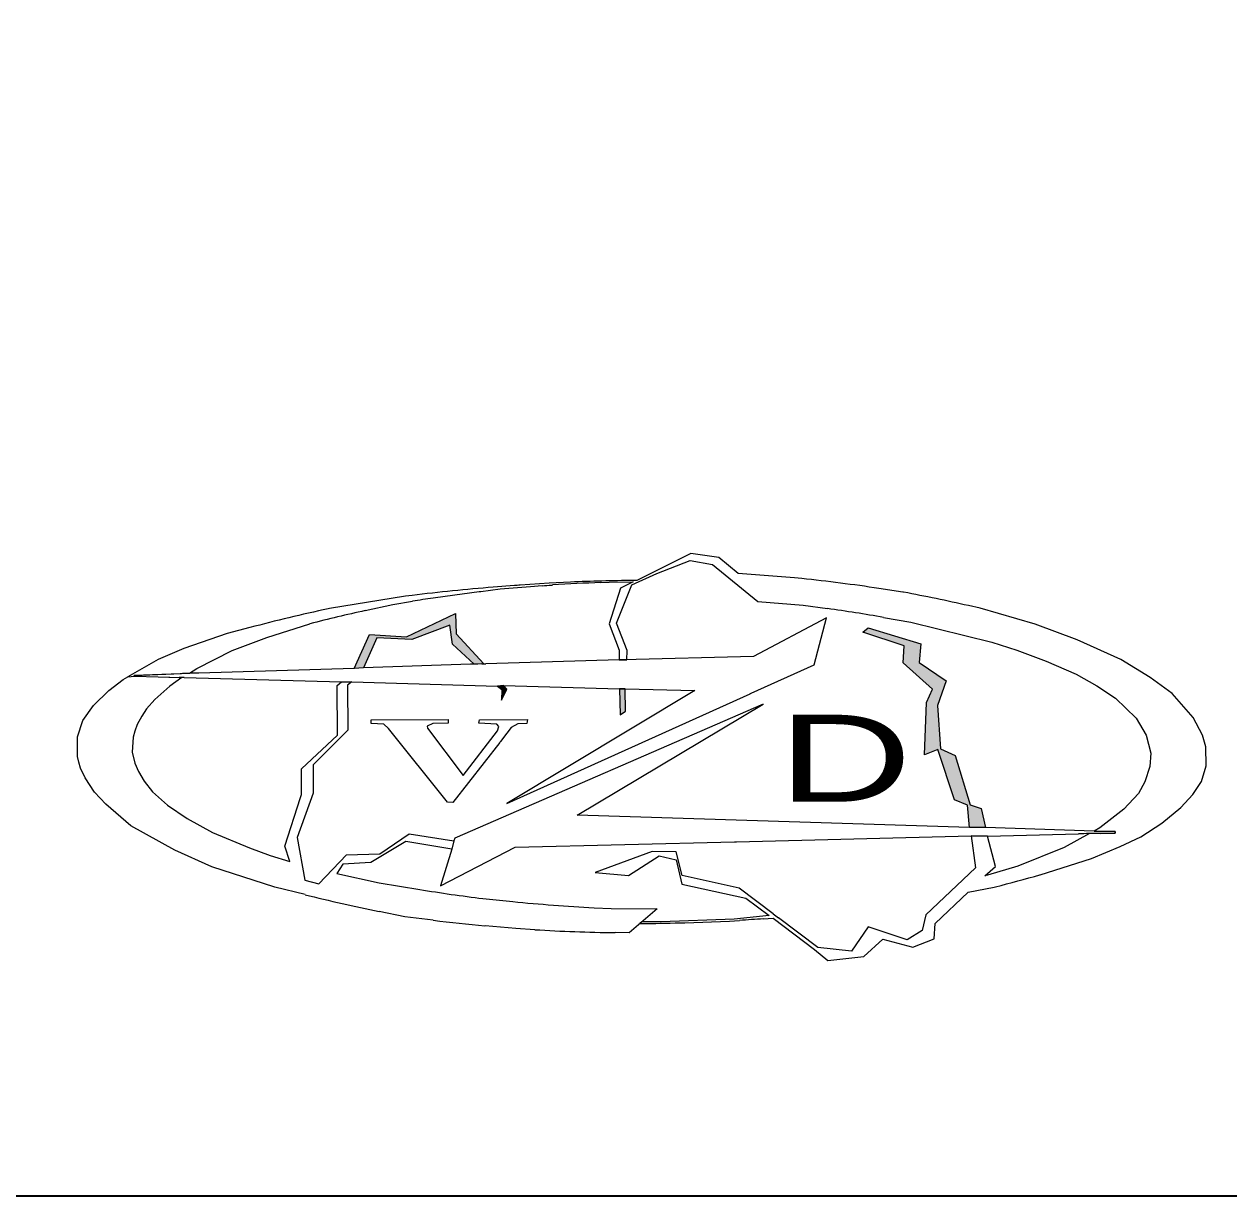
# Model space of a CAD drawing. Extents: x 308460 to 314812, y 245206 to 253414.
# Drawn here: x 314169.2 to 314384.6, y 245420.8 to 245630.3 of the extents above; entities that cross this region are included whole.
import ezdxf
from ezdxf.enums import TextEntityAlignment as Align

# ---------------------------------------------------------------- set-up
doc = ezdxf.new("R2010")
doc.units = 0
doc.header["$LTSCALE"] = 11
doc.layers.add('57', color=7, linetype='Continuous', lineweight=13)

msp = doc.modelspace()

# ---------------------------------------------------------------- hatches: boundary and pattern name
at = {"layer": '57'}
for points in [[(314229.92, 245515.24), (314228.22, 245515.09), (314230.98, 245521.15), (314237.58, 245520.76), (314246.36, 245524.93), (314246.46, 245521.3), (314251.41, 245515.91), (314249.66, 245515.86), (314245.78, 245519.45), (314245.34, 245522.85), (314238.55, 245520.28), (314232.29, 245520.57)], [(314341.08, 245486.67), (314338.25, 245486.67), (314337.84, 245490.68), (314335.54, 245491.62), (314332.59, 245500.58), (314330.17, 245499.64), (314330.52, 245509.01), (314331.59, 245511.42), (314326.34, 245516.08), (314326.57, 245519.14), (314319.14, 245521.56), (314320.09, 245522.38), (314329.52, 245519.49), (314329.23, 245516.14), (314334.06, 245512.9), (314332.53, 245508.48), (314333.06, 245500.7), (314335.65, 245499.52), (314338.37, 245490.74), (314340.31, 245490.03)], [(314254.93, 245512.08), (314253.88, 245511.95), (314254.62, 245511.35), (314254.57, 245509.44), (314255.5, 245511.4)], [(314276.66, 245511.43), (314275.65, 245511.44), (314275.77, 245506.8), (314276.71, 245507.47)]]:
    msp.add_hatch(color=256, dxfattribs=at).paths.add_polyline_path(points)

# ---------------------------------------------------------------- linework, layer by layer
for p, q in [((314256.87, 245529.91), (314253.1, 245529.62)), ((314263.49, 245530.01), (314263.7, 245530.02)), ((314251.07, 245515.9), (314250.31, 245515.88)), ((314271.12, 245472.32), (314274.18, 245472.16))]:
    msp.add_line(p, q, dxfattribs=at)
at = {"layer": '57', "lineweight": 35}
msp.add_lwpolyline([(314811.5, 253140.4), (312000.01, 253140.4), (312000.01, 245420.78), (314811.5, 245420.78)], close=True, dxfattribs=at)
at = {"layer": '57'}
for points in [[(314308.25, 245531.17), (314306.96, 245531.3), (314296.88, 245532.09), (314293.43, 245534.96), (314288.39, 245535.64), (314278.78, 245530.83), (314278.1, 245530.83)], [(314272.34, 245530.47), (314273.83, 245530.52), (314278.13, 245530.61), (314275.85, 245529.43), (314273.79, 245523.08), (314275.59, 245518.35), (314275.63, 245516.64), (314276.99, 245516.64), (314277.03, 245518.3), (314275.1, 245523.17), (314277.86, 245530.04), (314282.34, 245532.1), (314288.32, 245534.38), (314292.31, 245533.68), (314300.4, 245527.06), (314308.48, 245526.41), (314312.84, 245525.8)], [(314250.9, 245528.88), (314254.32, 245529.34), (314259.76, 245529.78), (314261.85, 245529.91)], [(314266.89, 245530.53), (314263.09, 245530.36), (314257.91, 245529.99)], [(314326.45, 245528.74), (314326.3, 245528.76), (314322.03, 245529.41)], [(314238.58, 245528.16), (314237.41, 245528.02), (314223.81, 245525.82), (314223.58, 245525.77)], [(314230.21, 245525.45), (314235.16, 245526.54), (314238.65, 245527.11)], [(314242.34, 245527.7), (314244.52, 245528.03), (314250.59, 245528.84)], [(314350.82, 245478.19), (314350.83, 245478.19), (314360.03, 245481.09), (314365.17, 245483.27), (314368.87, 245485.01), (314372.62, 245487.41), (314376.01, 245490.26), (314378.14, 245492.56), (314379.7, 245494.91), (314380.54, 245497.68), (314380.49, 245501.1), (314379.87, 245503.17), (314378.19, 245506.35), (314374.44, 245510.61), (314370.53, 245513.51), (314365.28, 245516.7), (314357.5, 245520.22), (314349.96, 245523), (314340.13, 245525.86), (314338.02, 245526.34)], [(314209.6, 245522.42), (314205.5, 245521.33), (314197.79, 245518.68), (314193.2, 245516.7), (314187.76, 245513.6), (314188.93, 245513.7), (314188.93, 245513.84), (314198.8, 245514.23), (314200.1, 245515.11), (314206.41, 245518.3), (314212.61, 245520.62), (314220.28, 245523.08), (314220.33, 245523.09)], [(314299.2, 245510.67), (314310.44, 245515.76), (314312.68, 245524.15), (314299.61, 245517.25), (314276.31, 245516.64), (314275.63, 245516.64), (314251.75, 245515.92)], [(314322.86, 245524.23), (314327.71, 245523.39), (314342.2, 245519.79), (314346.67, 245518.39), (314351.93, 245516.38), (314357.28, 245514.1), (314360.96, 245512), (314364.34, 245509.81), (314368, 245506.19), (314369.8, 245503.2), (314370.62, 245499.98), (314370.47, 245497.58), (314369.57, 245494.81), (314368.45, 245492.71), (314365.83, 245489.95), (314361.55, 245486.58), (314360.49, 245485.99), (314364.25, 245485.96), (314364.25, 245485.64), (314359.66, 245485.58), (314355.17, 245483.06), (314346.87, 245479.73), (314341.47, 245478.13), (314340.96, 245478.01), (314342.85, 245479.68), (314341.42, 245485.13), (314338.55, 245485.18), (314339.29, 245479.45), (314330.42, 245471.07), (314329.74, 245468.26), (314327.1, 245466.6), (314320.09, 245468.89), (314317.15, 245464.55), (314311.12, 245465.23), (314304.1, 245470.48)], [(314197.14, 245514.16), (314193.87, 245514.03), (314188.93, 245513.84), (314188.99, 245513.7), (314193.19, 245513.6), (314196.97, 245513.5)], [(314249.02, 245515.85), (314229.92, 245515.24), (314228.22, 245515.09), (314200.47, 245514.28)], [(314219.45, 245474.65), (314214.05, 245475.99), (314202.81, 245479.61), (314196.19, 245482.61), (314188.33, 245486.98), (314183.83, 245490.85), (314181.8, 245493), (314180.15, 245495.55), (314179.29, 245497.26), (314179.03, 245498.37), (314178.76, 245499.38), (314178.76, 245502.9), (314179.72, 245505.77), (314181.64, 245508.49), (314184.35, 245511.15), (314186.96, 245513.12), (314187.76, 245513.6), (314188.99, 245513.7), (314197.4, 245513.49), (314195.27, 245511.95), (314192.61, 245509.55), (314191.12, 245507.9), (314190.27, 245506.57), (314189.47, 245505.08), (314189.04, 245503.86), (314188.72, 245502.84), (314188.56, 245500.13), (314189.03, 245498.16), (314189.67, 245496.67), (314190.68, 245494.97), (314192.17, 245493.05), (314194.84, 245490.65), (314198.35, 245488.26), (314202.91, 245485.76), (314209.52, 245483), (314213.19, 245481.67), (314216.76, 245480.55), (314215.82, 245483.33), (314218.64, 245492.04), (314218.79, 245492.59), (314218.84, 245497.13), (314225.27, 245503.19), (314225.21, 245512.04), (314225.94, 245512.69), (314227.81, 245512.69), (314227.06, 245512.13), (314227.12, 245504.04), (314220.88, 245497.88), (314220.88, 245492.78), (314218.02, 245484.9), (314219.39, 245477.25), (314221.94, 245476.56), (314226.86, 245481.79), (314232.84, 245481.97), (314238.07, 245485.52), (314246.05, 245484.3), (314245.66, 245482.78), (314237.48, 245484.18), (314231.23, 245480.43), (314226.23, 245480.13), (314225.15, 245478.41), (314232.72, 245476.74), (314239.95, 245475.57)], [(314197.84, 245513.48), (314225.94, 245512.69), (314227.81, 245512.69), (314253.88, 245511.95), (314254.93, 245512.08), (314275.65, 245511.44), (314276.66, 245511.43), (314289.11, 245511.18), (314255.5, 245490.94), (314298.99, 245510.58)], [(314301.35, 245508.74), (314246.22, 245484.77), (314246.05, 245484.3), (314245.66, 245482.78), (314243.65, 245476.21), (314256.99, 245483.15), (314296.2, 245484.11)], [(314361.63, 245485.61), (314364.25, 245485.64), (314364.25, 245485.96), (314360.49, 245485.99), (314341.08, 245486.67), (314338.25, 245486.67), (314268.11, 245488.88), (314301.35, 245508.74)], [(314231.24, 245505.27), (314231.24, 245505.9), (314245.03, 245505.96), (314245.03, 245505.33), (314242.29, 245505.28), (314241.26, 245504.76), (314241.32, 245504.42), (314247.71, 245495.93), (314253.86, 245503.96), (314254.09, 245504.71), (314253.75, 245505.11), (314250.5, 245505.33), (314250.61, 245505.9), (314259.23, 245505.96), (314259.11, 245505.28), (314257.46, 245505.22), (314256.32, 245504.54), (314255.52, 245503.51), (314254.39, 245502.06)], [(314254.25, 245501.88), (314245.88, 245491.14), (314244.91, 245491.2), (314234.36, 245504.36), (314233.56, 245505.11), (314231.24, 245505.27)], [(314296.57, 245484.11), (314338.55, 245485.18), (314341.42, 245485.13), (314357.7, 245485.54)], [(314281.48, 245482.38), (314271.34, 245478.6), (314277.26, 245478.1), (314282.78, 245481.62), (314285.79, 245480.9), (314286.82, 245476.55), (314298.23, 245474.02), (314302.43, 245470.93), (314296.17, 245470.29), (314283.1, 245469.82), (314279.64, 245469.79), (314279.27, 245469.47), (314280.4, 245469.49)], [(314303.1, 245471.23), (314297.06, 245475.79), (314286.88, 245478.08), (314285.79, 245482.33), (314281.48, 245482.38)], [(314301.37, 245470.32), (314303.11, 245470.42), (314310.53, 245464.83), (314312.88, 245462.87), (314319.32, 245463.6), (314322.71, 245466.67), (314328.08, 245465.27), (314331.89, 245466.73), (314332.11, 245469.47), (314337.96, 245475.12), (314342.66, 245476.01), (314342.87, 245476.07)], [(314251.25, 245473.95), (314251.8, 245473.88), (314256.58, 245473.41)], [(314242.38, 245470.08), (314237.31, 245470.7), (314232.71, 245471.64)], [(314274.18, 245472.16), (314282.37, 245472.14), (314277.37, 245467.83), (314274.87, 245467.86)], [(314260.52, 245468.38), (314257.14, 245468.58), (314251.62, 245469.09)], [(314287.32, 245469.64), (314295.35, 245469.92), (314297.12, 245470.04)]]:
    msp.add_lwpolyline(points, dxfattribs=at)
for points in [[(314229.92, 245515.24), (314228.22, 245515.09), (314230.98, 245521.15), (314237.58, 245520.76), (314246.36, 245524.93), (314246.46, 245521.3), (314251.41, 245515.91), (314249.66, 245515.86), (314245.78, 245519.45), (314245.34, 245522.85), (314238.55, 245520.28), (314232.29, 245520.57)], [(314341.08, 245486.67), (314338.25, 245486.67), (314337.84, 245490.68), (314335.54, 245491.62), (314332.59, 245500.58), (314330.17, 245499.64), (314330.52, 245509.01), (314331.59, 245511.42), (314326.34, 245516.08), (314326.57, 245519.14), (314319.14, 245521.56), (314320.09, 245522.38), (314329.52, 245519.49), (314329.23, 245516.14), (314334.06, 245512.9), (314332.53, 245508.48), (314333.06, 245500.7), (314335.65, 245499.52), (314338.37, 245490.74), (314340.31, 245490.03)], [(314254.93, 245512.08), (314253.88, 245511.95), (314254.62, 245511.35), (314254.57, 245509.44), (314255.5, 245511.4)], [(314276.66, 245511.43), (314275.65, 245511.44), (314275.77, 245506.8), (314276.71, 245507.47)]]:
    msp.add_lwpolyline(points, close=True, dxfattribs=at)
for centre, start, end in [((314276.9, 245219.49), 94.3875, 97.0766), ((314280.67, 245219.78), 94.1949, 94.3875), ((314243.15, 245840.38), 273.4459, 273.7492), ((314284.04, 245219.65), 92.1565, 93.7492), ((314280.69, 245219.8), 90.4758, 92.5431), ((314275.7, 245221.84), 81.4326, 83.993), ((314289.1, 245220.19), 98.6469, 99.3347), ((314209.37, 245837.14), 277.616, 277.6734), ((314269.08, 245223.03), 77.1951, 79.3709), ((314289.16, 245221.72), 102.1714, 104.8197), ((314297.36, 245221.74), 102.4671, 104.3377), ((314269.68, 245217.77), 80.1552, 82.0251), ((314209.55, 245203.37), 91.6733, 92.2865), ((314258.94, 245204.96), 91.5901, 91.8283), ((314242.44, 245826.82), 271.5901, 271.7162), ((314189.1, 245202.56), 88.3913, 88.5507), ((314170.99, 245794.06), 294.3, 294.3419), ((314008.93, 245693.1), 322.0647, 322.1065), ((314288.65, 245795.05), 271.3916, 271.4597), ((314365.51, 245174.59), 90.7157, 91.4403), ((314266.53, 245777.59), 284.2068, 285.7221), ((314289.66, 245782.61), 260.8019, 262.9067), ((314294.84, 245776.41), 255.9728, 258.4773), ((314287.2, 245782.94), 264.3493, 267.0359), ((314490.34, 245719.6), 232.988, 233.2185), ((314280.2, 245778.81), 263.0161, 264.727), ((314276.73, 245780.5), 270.6772, 271.9512), ((314319.36, 245159.8), 93.3156, 94.1004), ((314278.88, 245778.88), 266.6159, 269.2612)]:
    msp.add_arc(centre, 311.04, start, end, dxfattribs=at)

# ---------------------------------------------------------------- texts
at = {"layer": '57', "width": 1.6}
msp.add_text('D', height=15.55, dxfattribs=at).set_placement((314315.96, 245491.28), align=Align.CENTER)

doc.saveas('drawing.dxf')
